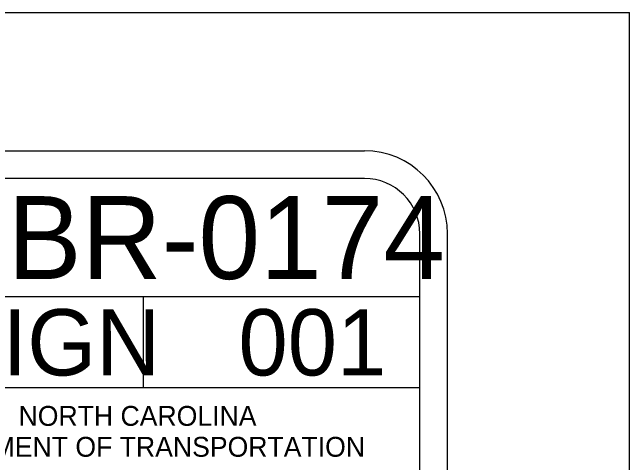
# Model space of a CAD drawing. Extents: x -2362 to 1945, y 0 to 1100.
# Drawn here: x 1588.3 to 1700, y 1018.5 to 1100 of the extents above; entities that cross this region are included whole.
import ezdxf

# ---------------------------------------------------------------- set-up
doc = ezdxf.new("R2010")
doc.units = 0
for name, color, linetype in [('Exist Utilities Power Test Hole SUE LOS A CELL', 7, 'Continuous'), ('Exist Utilities Telephone Test Hole SUE LOS A CELL', 7, 'Continuous'), ('Sheet PE Seal CELL', 7, 'Continuous'), ('z - Construction', 7, 'Continuous')]:
    doc.layers.add(name, color=color, linetype=linetype)

msp = doc.modelspace()

# ---------------------------------------------------------------- linework, layer by layer
at = {"layer": 'Exist Utilities Telephone Test Hole SUE LOS A CELL'}
for p in [(0, 1100), (1699.98, 0)]:
    msp.add_line(p, (1699.98, 1100), dxfattribs=at)
at = {"layer": 'Sheet PE Seal CELL'}
for p, q in [((1662, 1048.51), (1562, 1048.51)), ((1612, 1032.01), (1612, 1048.51)), ((1662, 1032.01), (1562, 1032.01))]:
    msp.add_line(p, q, dxfattribs=at)
for centre in [(1612, 1059.22), (1612, 1059.22), (1637, 1040.26), (1637, 1040.26)]:
    msp.add_circle(centre, 0.06, dxfattribs=at)
at = {"layer": 'z - Construction'}
for p, q in [((38.08, 1074.94), (1651.98, 1074.94)), ((1651.98, 1069.93), (1572, 1069.93)), ((1662, 39.96), (1662, 1059.91)), ((1667, 39.99), (1667, 1059.91))]:
    msp.add_line(p, q, dxfattribs=at)
for centre, radius, start, end in [((1651.97, 1059.92), 15.03, 359.9737, 89.9737), ((1651.98, 1059.91), 10.02, 0, 90)]:
    msp.add_arc(centre, radius, start, end, dxfattribs=at)

# ---------------------------------------------------------------- texts
at = {"layer": 'Exist Utilities Power Test Hole SUE LOS A CELL'}
for s, height, p in [('BR-0174', 15, (1587.4, 1051.72)), ('SIGN', 12, (1575.79, 1034.26)), ('001', 12, (1629.17, 1034.26))]:
    msp.add_text(s, height=height, dxfattribs=at).set_placement(p)
at = {"layer": 'Sheet PE Seal CELL'}
for s, p in [('NORTH CAROLINA', (1589.38, 1025.14)), ('DEPARTMENT OF TRANSPORTATION', (1565.16, 1019.54))]:
    msp.add_text(s, height=3.6, rotation=0, dxfattribs=at).set_placement(p)

doc.saveas('drawing.dxf')
